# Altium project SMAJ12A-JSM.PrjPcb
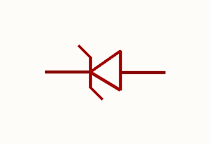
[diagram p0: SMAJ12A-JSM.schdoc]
1 sheet, 1 parts. Net scope: global (net labels, ports and power ports of the same name join across sheets).

## Sheet SMAJ12A-JSM.schdoc
size 127 x 101 mm

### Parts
D?  smaj12a-jsm  [SMA_L4.4-W2.8-LS5.1-RD]  (value not drawn)

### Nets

Not connected (* = marked no-connect by the designer): D? 1(C) 2(A)

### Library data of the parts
D? = smaj12a-jsm: 极性:单向;反向截止电压(Vrwm):13V;钳位电压:19.9V;峰值脉冲电流(Ipp):20.1A;峰值脉冲功率(Ppp):400W;击穿电压(VBR):14.7V;; Manufacturer: JSMSEMI(杰盛微); AddInBom: yes; ModelId: f8f3054a417b436cb6ecf34e6ce93dff; ModelTransform: 200.787,110.236,0,0,0,0,0,0,0; Polarity: 单向; Reverse Stand-Off Voltage (Vrwm): 13V; Clamping Voltage: 19.9V; Peak Pulse Current (Ipp): 20.1A; Peak Pulse Power Dissipation (Ppp): 400W; Voltage - Breakdown: 14.7V; Reverse Leakage Current (Ir): 1uA; Number of Channels: 单路; Type: TVS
